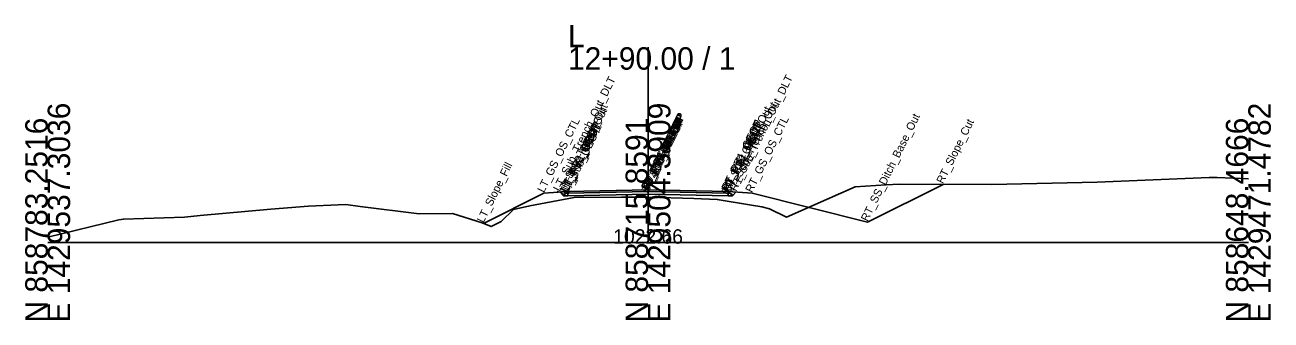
# Model space of a CAD drawing. Extents: x -26 to 2303, y -10 to 19558.
# Drawn here: x 1147.2 to 1302.8, y 5490.3 to 5527.2 of the extents above; entities that cross this region are included whole.
import ezdxf

# ---------------------------------------------------------------- set-up
doc = ezdxf.new("R2010")
doc.units = 0
for name, color, linetype in [('Default', 7, 'Continuous'), ('Exist Cross Section Cell', 7, 'Continuous'), ('Exist XS Center Line Elevation Label', 7, 'Continuous'), ('Exist XS Ground Line', 7, 'Continuous'), ('Prop CMT Pvmt Course 1', 7, 'Continuous'), ('Prop CMT Pvmt Course 2', 7, 'Continuous'), ('Prop CMT Pvmt Surface', 7, 'Continuous'), ('Prop CMT Pvmt Surface Shoulder', 7, 'Continuous'), ('Prop CMT Shld Paved Course 1', 7, 'Continuous'), ('Prop CMT Shld Paved Course 2', 7, 'Continuous'), ('Prop CMT Slope Grass', 7, 'Continuous'), ('Prop CMT Subgrade Earthwork', 7, 'Continuous'), ('Prop XS Dump Level', 7, 'Continuous')]:
    doc.layers.add(name, color=color, linetype=linetype)

msp = doc.modelspace()

# ---------------------------------------------------------------- linework, layer by layer
at = {"layer": 'Exist Cross Section Cell'}
for p, q in [((1225, 5500), (1225, 5524.41)), ((1150, 5500), (1225, 5500)), ((1225, 5500), (1300, 5500))]:
    msp.add_line(p, q, dxfattribs=at)
at = {"layer": 'Exist XS Ground Line'}
msp.add_lwpolyline([(1150, 5500.67), (1158.9, 5502.82), (1159.47, 5502.93), (1167.1, 5503.19), (1169.05, 5503.39), (1177.89, 5504.17), (1182.59, 5504.56), (1186.29, 5504.72), (1187.24, 5504.74), (1189.06, 5504.52), (1196.4, 5503.61), (1200.59, 5503.64), (1204.28, 5502.46), (1205.42, 5502), (1206.65, 5502.65), (1208.2, 5504.12), (1210.25, 5504.58), (1215.77, 5505.62), (1221.68, 5505.66), (1224.68, 5505.67), (1225, 5505.66), (1230.71, 5505.49), (1233.66, 5505.4), (1237.94, 5504.68), (1239.23, 5504.48), (1240.17, 5504.2), (1242.3, 5503.18), (1250.89, 5506.98), (1254.74, 5507.21), (1256.39, 5507.28), (1267.95, 5507.25), (1281.1, 5507.56), (1295.11, 5508.14), (1296.1, 5508.13), (1300, 5507.97)], dxfattribs=at)
at = {"layer": 'Prop CMT Pvmt Course 1'}
for points in [[(1225, 5506.6), (1215, 5506.4)], [(1225, 5506.39), (1225, 5506.6)], [(1225, 5506.6), (1235, 5506.4)], [(1225, 5506.39), (1225, 5506.6)], [(1215, 5506.4), (1215, 5506.19)], [(1215, 5506.19), (1225, 5506.39)], [(1235, 5506.19), (1225, 5506.39)], [(1235, 5506.4), (1235, 5506.19)]]:
    msp.add_lwpolyline(points, dxfattribs=at)
msp.add_lwpolyline([(1225, 5506.39), (1225, 5506.48), (1225, 5506.48), (1225, 5506.39)], close=True, dxfattribs=at)
msp.add_lwpolyline([(1225, 5506.39), (1225, 5506.48), (1225, 5506.48), (1225, 5506.39)], close=True, dxfattribs=at)
at = {"layer": 'Prop CMT Pvmt Course 2'}
for points in [[(1225, 5506.39), (1215, 5506.19)], [(1215, 5506.19), (1215, 5505.86)], [(1215, 5505.86), (1225, 5506.06)], [(1225, 5506.06), (1225, 5506.39)], [(1225, 5506.06), (1225, 5506.39)], [(1225, 5506.39), (1235, 5506.19)], [(1235, 5505.86), (1225, 5506.06)], [(1235, 5506.19), (1235, 5505.86)]]:
    msp.add_lwpolyline(points, dxfattribs=at)
at = {"layer": 'Prop CMT Pvmt Surface'}
for points in [[(1225, 5506.6), (1215, 5506.4)], [(1225, 5506.6), (1235, 5506.4)]]:
    msp.add_lwpolyline(points, dxfattribs=at)
at = {"layer": 'Prop CMT Pvmt Surface Shoulder'}
for points in [[(1215, 5506.4), (1215, 5506.4)], [(1235, 5506.4), (1235, 5506.4)]]:
    msp.add_lwpolyline(points, dxfattribs=at)
at = {"layer": 'Prop CMT Shld Paved Course 1'}
for points in [[(1215, 5506.4), (1214.79, 5506.19)], [(1214.79, 5506.19), (1215, 5506.19)], [(1215, 5506.4), (1215, 5506.4)], [(1215, 5506.19), (1215, 5506.4)], [(1235, 5506.4), (1235, 5506.4)], [(1235, 5506.4), (1235.21, 5506.19)], [(1235, 5506.19), (1235, 5506.4)], [(1235.21, 5506.19), (1235, 5506.19)]]:
    msp.add_lwpolyline(points, dxfattribs=at)
at = {"layer": 'Prop CMT Shld Paved Course 2'}
for points in [[(1214.79, 5506.19), (1214.45, 5505.85)], [(1214.45, 5505.85), (1215, 5505.86)], [(1215, 5506.19), (1214.79, 5506.19)], [(1214.79, 5506.19), (1214.79, 5506.19)], [(1215, 5505.86), (1215, 5506.19)], [(1235, 5506.19), (1235.21, 5506.19)], [(1235, 5505.86), (1235, 5506.19)], [(1235.55, 5505.85), (1235, 5505.86)], [(1235.21, 5506.19), (1235.21, 5506.19)], [(1235.21, 5506.19), (1235.55, 5505.85)]]:
    msp.add_lwpolyline(points, dxfattribs=at)
at = {"layer": 'Prop CMT Slope Grass'}
for points in [[(1235, 5506.4), (1238, 5506.16), (1252.43, 5502.56), (1261.86, 5507.27)], [(1215, 5506.4), (1212, 5506.16), (1204.45, 5502.39)]]:
    msp.add_lwpolyline(points, dxfattribs=at)
at = {"layer": 'Prop CMT Subgrade Earthwork'}
for points in [[(1214.45, 5505.85), (1213.98, 5506.32)], [(1215, 5505.86), (1214.45, 5505.85)], [(1225, 5506.06), (1215, 5505.86)], [(1225, 5506.06), (1235, 5505.86)], [(1235, 5505.86), (1235.55, 5505.85)], [(1235.55, 5505.85), (1236.02, 5506.32)]]:
    msp.add_lwpolyline(points, dxfattribs=at)

# ---------------------------------------------------------------- texts
at = {"layer": 'Default'}
msp.add_text('-', height=0.0001, dxfattribs=at).set_placement((1150, 5500))
at = {"layer": 'Exist Cross Section Cell'}
for s, p in [('L', (1215, 5524.41)), ('12+90.00 / 1', (1215, 5521.61))]:
    msp.add_text(s, height=2.8, dxfattribs=at).set_placement(p)
for s, p in [('E 1429537.3036', (1152.8, 5490)), ('E 1429504.3909', (1227.8, 5490)), ('E 1429471.4782', (1302.8, 5490)), ('N 858783.2516', (1150, 5490)), ('N 858715.8591', (1225, 5490)), ('N 858648.4666', (1300, 5490))]:
    msp.add_text(s, height=2.8, rotation=90, dxfattribs=at).set_placement(p)
at = {"layer": 'Exist XS Center Line Elevation Label'}
msp.add_text('1022.66', height=1.8, dxfattribs=at).set_placement((1220.66, 5499.86))
at = {"layer": 'Prop XS Dump Level'}
for s, p in [('LT_Sub_Trench_Out_DLT', (1213.98, 5506.32)), ('RT_Sub_Trench_Out_DLT', (1236.02, 5506.32)), ('LT_Sub_Trench_Out', (1214.45, 5505.85)), ('RT_Sub_Trench_Out', (1235.55, 5505.85)), ('LT_PS2_Shelf_Out', (1214.79, 5506.19)), ('RT_PV1_OEEOP', (1225, 5506.48)), ('RT_PV2_OEEOP', (1225, 5506.39)), ('LT_PV1_OEEOP', (1225, 5506.48)), ('LT_PV2_OEEOP', (1225, 5506.39)), ('RT_PS2_Shelf_Out', (1235.21, 5506.19)), ('RT_SS_Ditch_Base_Out', (1252.43, 5502.56)), ('LT_GS_OS_CTL', (1212, 5506.16)), ('LT_PS2_OEOP', (1214.79, 5506.19)), ('LT_PV1_OEOT', (1215, 5506.4)), ('LT_PS1_OEOP', (1215, 5506.4)), ('LT_PV2_OEOT', (1215, 5506.19)), ('LT_Sub_OEOT', (1215, 5505.86)), ('RT_Sub_OEEOP', (1225, 5506.06)), ('RT_PV1_IEEOP', (1225, 5506.48)), ('RT_PV2_IEEOP', (1225, 5506.39)), ('LT_Sub_OEEOP', (1225, 5506.06)), ('LT_PV1_IEEOP', (1225, 5506.48)), ('LT_PV2_IEEOP', (1225, 5506.39)), ('RT_PV1_OEOT', (1235, 5506.4)), ('RT_PS1_OEOP', (1235, 5506.4)), ('RT_PV2_OEOT', (1235, 5506.19)), ('RT_Sub_OEOT', (1235, 5505.86)), ('RT_PS2_OEOP', (1235.21, 5506.19)), ('RT_GS_OS_CTL', (1238, 5506.16)), ('RT_Slope_Cut', (1261.86, 5507.27)), ('PV1_PGL', (1225, 5506.6)), ('PV2_PGL', (1225, 5506.39)), ('LT_Slope_Fill', (1204.45, 5502.39))]:
    msp.add_text(s, height=1, rotation=63.5833, dxfattribs=at).set_placement(p)

doc.saveas('drawing.dxf')
